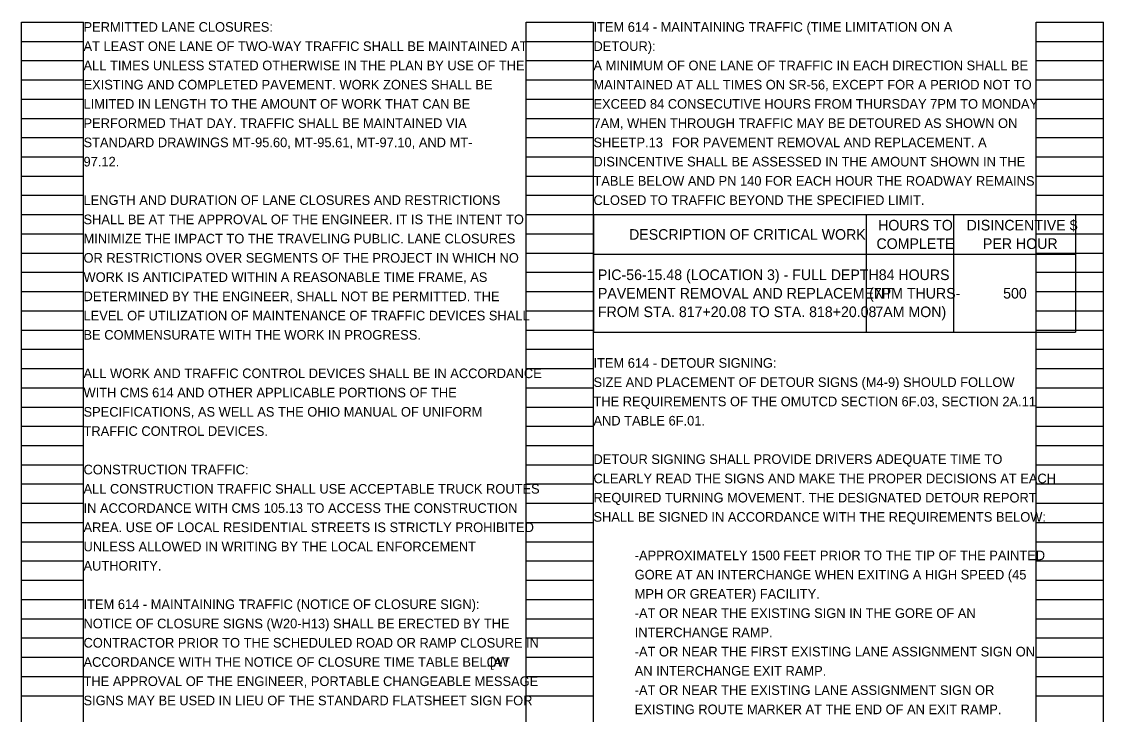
# Model space of a CAD drawing. Extents: x 24172 to 24226.9, y 11011.9 to 11091.2.
# Drawn here: x 24196.45 to 24212.19, y 11052.04 to 11062.11 of the extents above; entities that cross this region are included whole.
import ezdxf

# ---------------------------------------------------------------- set-up
doc = ezdxf.new("R2010")
doc.units = 0
doc.layers.add('SC_Scratch1', color=7, linetype='Continuous')
doc.layers.add('SH_Data', color=7, linetype='Continuous')

msp = doc.modelspace()

# ---------------------------------------------------------------- linework, layer by layer
at = {"layer": 'SH_Data'}
for p, q in [((24196.45, 11041.947), (24196.45, 11062.107)), ((24196.45, 11062.107), (24197.35, 11062.107)), ((24197.35, 11041.947), (24197.35, 11062.107)), ((24203.79, 11041.947), (24203.79, 11062.107)), ((24203.79, 11062.107), (24204.77, 11062.107)), ((24204.77, 11041.947), (24204.77, 11062.107)), ((24211.21, 11041.947), (24211.21, 11062.107)), ((24211.21, 11062.107), (24212.19, 11062.107)), ((24212.19, 11041.947), (24212.19, 11062.107)), ((24196.45, 11061.827), (24197.35, 11061.827)), ((24203.79, 11061.827), (24204.77, 11061.827)), ((24211.21, 11061.827), (24212.19, 11061.827)), ((24196.45, 11061.547), (24197.35, 11061.547)), ((24203.79, 11061.547), (24204.77, 11061.547)), ((24211.21, 11061.547), (24212.19, 11061.547)), ((24196.45, 11061.267), (24197.35, 11061.267)), ((24203.79, 11061.267), (24204.77, 11061.267)), ((24211.21, 11061.267), (24212.19, 11061.267)), ((24196.45, 11060.987), (24197.35, 11060.987)), ((24203.79, 11060.987), (24204.77, 11060.987)), ((24211.21, 11060.987), (24212.19, 11060.987)), ((24196.45, 11060.707), (24197.35, 11060.707)), ((24203.79, 11060.707), (24204.77, 11060.707)), ((24211.21, 11060.707), (24212.19, 11060.707)), ((24196.45, 11060.427), (24197.35, 11060.427)), ((24203.79, 11060.427), (24204.77, 11060.427)), ((24211.21, 11060.427), (24212.19, 11060.427)), ((24196.45, 11060.147), (24197.35, 11060.147)), ((24203.79, 11060.147), (24204.77, 11060.147)), ((24211.21, 11060.147), (24212.19, 11060.147)), ((24196.45, 11059.867), (24197.35, 11059.867)), ((24203.79, 11059.867), (24204.77, 11059.867)), ((24211.21, 11059.867), (24212.19, 11059.867)), ((24196.45, 11059.587), (24197.35, 11059.587)), ((24203.79, 11059.587), (24204.77, 11059.587)), ((24211.21, 11059.587), (24212.19, 11059.587)), ((24196.45, 11059.307), (24197.35, 11059.307)), ((24203.79, 11059.307), (24204.77, 11059.307)), ((24204.77, 11059.307), (24211.786, 11059.307)), ((24204.77, 11059.307), (24204.77, 11057.594)), ((24208.739, 11059.307), (24208.739, 11057.594)), ((24210.007, 11059.307), (24210.007, 11057.594)), ((24211.21, 11059.307), (24212.19, 11059.307)), ((24211.786, 11059.307), (24211.786, 11057.594)), ((24196.45, 11059.027), (24197.35, 11059.027)), ((24203.79, 11059.027), (24204.77, 11059.027)), ((24211.21, 11059.027), (24212.19, 11059.027)), ((24196.45, 11058.747), (24197.35, 11058.747)), ((24203.79, 11058.747), (24204.77, 11058.747)), ((24204.77, 11058.73), (24211.786, 11058.73)), ((24211.21, 11058.747), (24212.19, 11058.747)), ((24196.45, 11058.467), (24197.35, 11058.467)), ((24203.79, 11058.467), (24204.77, 11058.467)), ((24211.21, 11058.467), (24212.19, 11058.467)), ((24196.45, 11058.187), (24197.35, 11058.187)), ((24203.79, 11058.187), (24204.77, 11058.187)), ((24211.21, 11058.187), (24212.19, 11058.187)), ((24196.45, 11057.907), (24197.35, 11057.907)), ((24203.79, 11057.907), (24204.77, 11057.907)), ((24211.21, 11057.907), (24212.19, 11057.907)), ((24196.45, 11057.627), (24197.35, 11057.627)), ((24203.79, 11057.627), (24204.77, 11057.627)), ((24204.77, 11057.594), (24211.786, 11057.594)), ((24211.21, 11057.627), (24212.19, 11057.627)), ((24196.45, 11057.347), (24197.35, 11057.347)), ((24203.79, 11057.347), (24204.77, 11057.347)), ((24211.21, 11057.347), (24212.19, 11057.347)), ((24196.45, 11057.067), (24197.35, 11057.067)), ((24203.79, 11057.067), (24204.77, 11057.067)), ((24211.21, 11057.067), (24212.19, 11057.067)), ((24196.45, 11056.787), (24197.35, 11056.787)), ((24203.79, 11056.787), (24204.77, 11056.787)), ((24211.21, 11056.787), (24212.19, 11056.787)), ((24196.45, 11056.507), (24197.35, 11056.507)), ((24203.79, 11056.507), (24204.77, 11056.507)), ((24211.21, 11056.507), (24212.19, 11056.507)), ((24196.45, 11056.227), (24197.35, 11056.227)), ((24203.79, 11056.227), (24204.77, 11056.227)), ((24211.21, 11056.227), (24212.19, 11056.227)), ((24196.45, 11055.947), (24197.35, 11055.947)), ((24203.79, 11055.947), (24204.77, 11055.947)), ((24211.21, 11055.947), (24212.19, 11055.947)), ((24196.45, 11055.667), (24197.35, 11055.667)), ((24203.79, 11055.667), (24204.77, 11055.667)), ((24211.21, 11055.667), (24212.19, 11055.667)), ((24196.45, 11055.387), (24197.35, 11055.387)), ((24203.79, 11055.387), (24204.77, 11055.387)), ((24211.21, 11055.387), (24212.19, 11055.387)), ((24196.45, 11055.107), (24197.35, 11055.107)), ((24203.79, 11055.107), (24204.77, 11055.107)), ((24211.21, 11055.107), (24212.19, 11055.107)), ((24196.45, 11054.827), (24197.35, 11054.827)), ((24203.79, 11054.827), (24204.77, 11054.827)), ((24211.21, 11054.827), (24212.19, 11054.827)), ((24196.45, 11054.547), (24197.35, 11054.547)), ((24203.79, 11054.547), (24204.77, 11054.547)), ((24211.21, 11054.547), (24212.19, 11054.547)), ((24196.45, 11054.267), (24197.35, 11054.267)), ((24203.79, 11054.267), (24204.77, 11054.267)), ((24211.21, 11054.267), (24212.19, 11054.267)), ((24196.45, 11053.987), (24197.35, 11053.987)), ((24203.79, 11053.987), (24204.77, 11053.987)), ((24211.21, 11053.987), (24212.19, 11053.987)), ((24196.45, 11053.707), (24197.35, 11053.707)), ((24203.79, 11053.707), (24204.77, 11053.707)), ((24211.21, 11053.707), (24212.19, 11053.707)), ((24196.45, 11053.427), (24197.35, 11053.427)), ((24203.79, 11053.427), (24204.77, 11053.427)), ((24211.21, 11053.427), (24212.19, 11053.427)), ((24196.45, 11053.147), (24197.35, 11053.147)), ((24203.79, 11053.147), (24204.77, 11053.147)), ((24211.21, 11053.147), (24212.19, 11053.147)), ((24196.45, 11052.867), (24197.35, 11052.867)), ((24203.79, 11052.867), (24204.77, 11052.867)), ((24211.21, 11052.867), (24212.19, 11052.867)), ((24196.45, 11052.587), (24197.35, 11052.587)), ((24203.79, 11052.587), (24204.77, 11052.587)), ((24211.21, 11052.587), (24212.19, 11052.587)), ((24196.45, 11052.307), (24197.35, 11052.307)), ((24203.79, 11052.307), (24204.77, 11052.307)), ((24211.21, 11052.307), (24212.19, 11052.307))]:
    msp.add_line(p, q, dxfattribs=at)

# ---------------------------------------------------------------- texts
at = {"layer": 'SC_Scratch1'}
for s, p in [('PERMITTED LANE CLOSURES:', (24197.35, 11061.967)), ('ITEM 614 - MAINTAINING TRAFFIC (TIME LIMITATION ON A ', (24204.77, 11061.967)), ('AT LEAST ONE LANE OF TWO-WAY TRAFFIC SHALL BE MAINTAINED AT ', (24197.35, 11061.687)), ('DETOUR):', (24204.77, 11061.687)), ('ALL TIMES UNLESS STATED OTHERWISE IN THE PLAN BY USE OF THE ', (24197.35, 11061.407)), ('A MINIMUM OF ONE LANE OF TRAFFIC IN EACH DIRECTION SHALL BE ', (24204.77, 11061.407)), ('EXISTING AND COMPLETED PAVEMENT. WORK ZONES SHALL BE ', (24197.35, 11061.127)), ('MAINTAINED AT ALL TIMES ON SR-56, EXCEPT FOR A PERIOD NOT TO ', (24204.77, 11061.127)), ('LIMITED IN LENGTH TO THE AMOUNT OF WORK THAT CAN BE ', (24197.35, 11060.847)), ('EXCEED 84 CONSECUTIVE HOURS FROM THURSDAY 7PM TO MONDAY ', (24204.77, 11060.847)), ('PERFORMED THAT DAY. TRAFFIC SHALL BE MAINTAINED VIA ', (24197.35, 11060.567)), ('7AM, WHEN THROUGH TRAFFIC MAY BE DETOURED AS SHOWN ON ', (24204.77, 11060.567)), ('STANDARD DRAWINGS MT-95.60, MT-95.61, MT-97.10, AND MT-', (24197.35, 11060.287)), ('SHEET          FOR PAVEMENT REMOVAL AND REPLACEMENT. A ', (24204.77, 11060.287)), ('97.12. ', (24197.35, 11060.007)), ('DISINCENTIVE SHALL BE ASSESSED IN THE AMOUNT SHOWN IN THE ', (24204.77, 11060.007)), ('TABLE BELOW AND PN 140 FOR EACH HOUR THE ROADWAY REMAINS ', (24204.77, 11059.727)), ('LENGTH AND DURATION OF LANE CLOSURES AND RESTRICTIONS ', (24197.35, 11059.447)), ('CLOSED TO TRAFFIC BEYOND THE SPECIFIED LIMIT.', (24204.77, 11059.447)), ('SHALL BE AT THE APPROVAL OF THE ENGINEER. IT IS THE INTENT TO ', (24197.35, 11059.167)), ('MINIMIZE THE IMPACT TO THE TRAVELING PUBLIC. LANE CLOSURES ', (24197.35, 11058.887)), ('OR RESTRICTIONS OVER SEGMENTS OF THE PROJECT IN WHICH NO ', (24197.35, 11058.607)), ('WORK IS ANTICIPATED WITHIN A REASONABLE TIME FRAME, AS ', (24197.35, 11058.327)), ('DETERMINED BY THE ENGINEER, SHALL NOT BE PERMITTED. THE ', (24197.35, 11058.047)), ('LEVEL OF UTILIZATION OF MAINTENANCE OF TRAFFIC DEVICES SHALL ', (24197.35, 11057.767)), ('BE COMMENSURATE WITH THE WORK IN PROGRESS.', (24197.35, 11057.487)), ('ITEM 614 - DETOUR SIGNING:', (24204.77, 11057.078)), ('ALL WORK AND TRAFFIC CONTROL DEVICES SHALL BE IN ACCORDANCE ', (24197.35, 11056.927)), ('SIZE AND PLACEMENT OF DETOUR SIGNS (M4-9) SHOULD FOLLOW ', (24204.77, 11056.798)), ('WITH CMS 614 AND OTHER APPLICABLE PORTIONS OF THE ', (24197.35, 11056.647)), ('THE REQUIREMENTS OF THE OMUTCD SECTION 6F.03, SECTION 2A.11 ', (24204.77, 11056.518)), ('SPECIFICATIONS, AS WELL AS THE OHIO MANUAL OF UNIFORM ', (24197.35, 11056.367)), ('AND TABLE 6F.01.', (24204.77, 11056.238)), ('TRAFFIC CONTROL DEVICES.', (24197.35, 11056.087)), ('DETOUR SIGNING SHALL PROVIDE DRIVERS ADEQUATE TIME TO ', (24204.77, 11055.678)), ('CONSTRUCTION TRAFFIC:', (24197.35, 11055.527)), ('CLEARLY READ THE SIGNS AND MAKE THE PROPER DECISIONS AT EACH ', (24204.77, 11055.398)), ('ALL CONSTRUCTION TRAFFIC SHALL USE ACCEPTABLE TRUCK ROUTES ', (24197.35, 11055.247)), ('REQUIRED TURNING MOVEMENT. THE DESIGNATED DETOUR REPORT ', (24204.77, 11055.118)), ('IN ACCORDANCE WITH CMS 105.13 TO ACCESS THE CONSTRUCTION ', (24197.35, 11054.967)), ('SHALL BE SIGNED IN ACCORDANCE WITH THE REQUIREMENTS BELOW:', (24204.77, 11054.838)), ('AREA. USE OF LOCAL RESIDENTIAL STREETS IS STRICTLY PROHIBITED ', (24197.35, 11054.687)), ('UNLESS ALLOWED IN WRITING BY THE LOCAL ENFORCEMENT ', (24197.35, 11054.407)), ('-APPROXIMATELY 1500 FEET PRIOR TO THE TIP OF THE PAINTED ', (24205.37, 11054.278)), ('AUTHORITY.', (24197.35, 11054.127)), ('GORE AT AN INTERCHANGE WHEN EXITING A HIGH SPEED (45 ', (24205.37, 11053.998)), ('MPH OR GREATER) FACILITY.', (24205.37, 11053.718)), ('ITEM 614 - MAINTAINING TRAFFIC (NOTICE OF CLOSURE SIGN):', (24197.35, 11053.567)), ('-AT OR NEAR THE EXISTING SIGN IN THE GORE OF AN ', (24205.37, 11053.438)), ('NOTICE OF CLOSURE SIGNS (W20-H13) SHALL BE ERECTED BY THE ', (24197.35, 11053.287)), ('INTERCHANGE RAMP.', (24205.37, 11053.158)), ('CONTRACTOR PRIOR TO THE SCHEDULED ROAD OR RAMP CLOSURE IN ', (24197.35, 11053.007)), ('-AT OR NEAR THE FIRST EXISTING LANE ASSIGNMENT SIGN ON ', (24205.37, 11052.878)), ('ACCORDANCE WITH THE NOTICE OF CLOSURE TIME TABLE BELOW', (24197.35, 11052.727)), ('.[AT ', (24203.214, 11052.727)), ('AN INTERCHANGE EXIT RAMP.', (24205.37, 11052.598)), ('THE APPROVAL OF THE ENGINEER, PORTABLE CHANGEABLE MESSAGE ', (24197.35, 11052.447)), ('-AT OR NEAR THE EXISTING LANE ASSIGNMENT SIGN OR ', (24205.37, 11052.318)), ('SIGNS MAY BE USED IN LIEU OF THE STANDARD FLATSHEET SIGN FOR ', (24197.35, 11052.167)), ('EXISTING ROUTE MARKER AT THE END OF AN EXIT RAMP.', (24205.37, 11052.038))]:
    msp.add_text(s, height=0.14, dxfattribs=at).set_placement(p)
at = {"layer": 'SH_Data'}
for s, height, p in [('P.13', 0.14, (24205.396, 11060.287)), ('DISINCENTIVE $ ', 0.154, (24210.2, 11059.076)), ('DESCRIPTION OF CRITICAL WORK', 0.154, (24205.288, 11058.941)), ('HOURS TO ', 0.154, (24208.912, 11059.076)), ('COMPLETE', 0.154, (24208.888, 11058.807)), ('PER HOUR', 0.154, (24210.437, 11058.807)), ('PIC-56-15.48 (LOCATION 3) - FULL DEPTH ', 0.154, (24204.835, 11058.354)), ('84 HOURS ', 0.154, (24208.921, 11058.354)), ('PAVEMENT REMOVAL AND REPLACEMENT ', 0.154, (24204.835, 11058.085)), ('(7PM THURS-', 0.154, (24208.781, 11058.085)), ('500', 0.154, (24210.731, 11058.085)), ('FROM STA. 817+20.08 TO STA. 818+20.08', 0.154, (24204.835, 11057.815)), ('7AM MON)', 0.154, (24208.873, 11057.815))]:
    msp.add_text(s, height=height, dxfattribs=at).set_placement(p)

doc.saveas('drawing.dxf')
